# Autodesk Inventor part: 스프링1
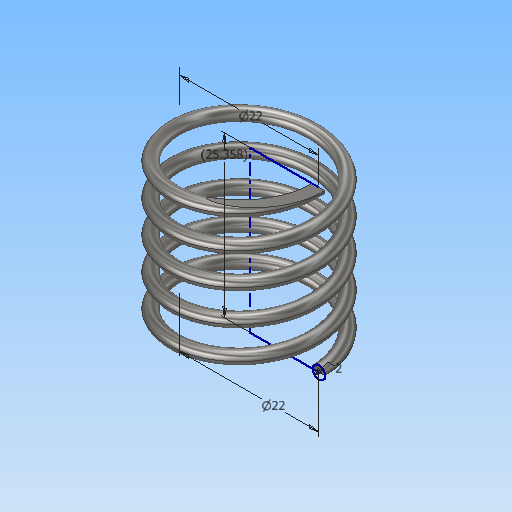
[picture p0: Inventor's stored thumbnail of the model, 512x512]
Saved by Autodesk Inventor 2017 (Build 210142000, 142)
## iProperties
Part Number: 스프링1
Material: 강철, 연강
Document SubType Name: Modeling
Designer: MRC
Density: 7.85 g/cm^3
Appearance: 반연마
Mass: 8.42324 g
Surface Area: 21.7217 cm^2
Volume: 1.07302 cm^3
Author: MRC
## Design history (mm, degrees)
sketch "스케치1"
  geometry: L1 (0, 0)-(0, 25.358); L2 (0, 25.358)-(11, 25.358); L3 (0, 0)-(11, 0); C1 r 1 at (11, 0)
  constraints: 6 end point, 2 horizontal, 1 centre point, 1 coincident, 1 vertical
  dimensions: "d0" = 25.35829 distance of L1.start L1.end (derived); "d2" = 22 diameter of L3.end L1; "d3" = 2 diameter of C1; "d4" = 22 diameter of L2.end L1
feature "코일1" pitch "d5" = 10; turns "d7" = 5; dims "d6" = 25.35829 (= d0), "d8" = 0, angle "d9" = 90 deg, angle "d10" = 90 deg, "d11" = 0, "d12" = 0
sketch "스케치2"
  geometry: L1 (-13.313, 0)-(15.035, 0); L2 (15.035, 0)-(15.035, 25.358); L3 (15.035, 25.358)-(-13.313, 25.358); L4 (-13.313, 25.358)-(-13.313, 0); 1 further point
  constraints: 8 end point, 2 parallel, 1 horizontal, 1 perpendicular
  dimensions: "d13" = 25.35829 distance of L1.end L2.end (= d0)
extrude "돌출1" sketch "스케치2" stored distance "d14" = 0; taper "d15" = 0 deg
node "솔리드1"
